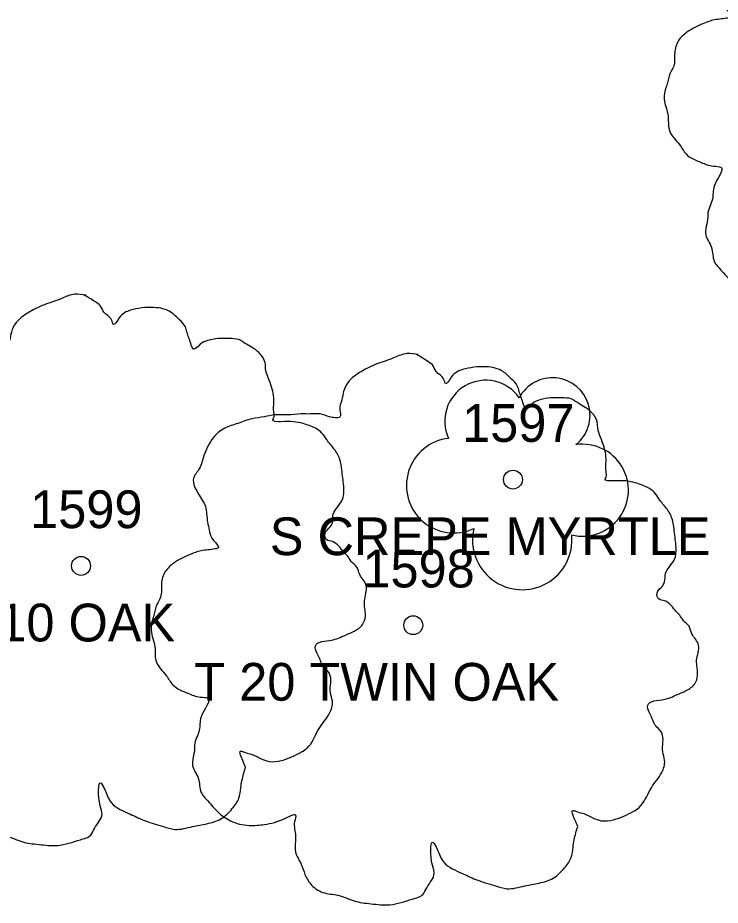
# Model space of a CAD drawing. Extents: x 1965304 to 1970247, y 1117014 to 1118201.
# Drawn here: x 1966620.94 to 1966639.53, y 1117434.12 to 1117457.62 of the extents above; entities that cross this region are included whole.
import ezdxf

# ---------------------------------------------------------------- set-up
doc = ezdxf.new("R2010")
doc.units = 0
doc.layers.add('RD_EX_VEG', color=7, linetype='Continuous')
doc.layers.add('RD_EX_VEG_txCode', color=7, linetype='Continuous')

msp = doc.modelspace()

# ---------------------------------------------------------------- linework, layer by layer
at = {"layer": 'RD_EX_VEG'}
for centre, radius in [((1966634.047, 1117445.393), 0.25), ((1966634.047, 1117445.393), 0.25), ((1966622.611, 1117443.108), 0.25), ((1966622.611, 1117443.108), 0.25), ((1966622.598, 1117443.09), 0.0001), ((1966622.598, 1117443.09), 0.0001), ((1966631.407, 1117441.538), 0.25), ((1966631.407, 1117441.538), 0.25), ((1966631.394, 1117441.519), 0.0001), ((1966631.394, 1117441.519), 0.0001)]:
    msp.add_circle(centre, radius, dxfattribs=at)
for centre, radius, start, end in [((1966633.325, 1117446.94), 1.084, 34.9763, 204.756), ((1966633.325, 1117446.94), 1.084, 34.9763, 204.756), ((1966635.092, 1117447.095), 0.995, 308.7626, 152.0467), ((1966635.092, 1117447.095), 0.995, 308.7626, 152.0467), ((1966632.483, 1117445.237), 1.257, 96.4518, 294.734), ((1966632.483, 1117445.237), 1.257, 96.4518, 294.734), ((1966635.886, 1117445.113), 1.218, 256.5667, 98.1046), ((1966635.886, 1117445.113), 1.218, 256.5667, 98.1046), ((1966634.292, 1117443.796), 1.318, 166.8827, 5.7589), ((1966634.292, 1117443.796), 1.318, 166.8827, 5.7589)]:
    msp.add_arc(centre, radius, start, end, dxfattribs=at)
for points in [[(1966645.126, 1117462.764), (1966644.826, 1117462.789), (1966644.501, 1117462.689), (1966644.251, 1117462.589), (1966644.026, 1117462.514), (1966643.801, 1117462.414), (1966643.501, 1117462.24), (1966643.276, 1117462.04), (1966643.151, 1117461.79), (1966643.101, 1117461.565), (1966643.052, 1117461.29), (1966643.052, 1117461.115), (1966642.927, 1117461.09), (1966642.777, 1117461.115), (1966642.527, 1117461.19), (1966642.277, 1117461.19), (1966642.027, 1117461.19), (1966641.677, 1117461.165), (1966641.327, 1117461.165), (1966641.052, 1117461.115), (1966640.728, 1117461.065), (1966640.353, 1117460.94), (1966640.003, 1117460.815), (1966639.703, 1117460.565), (1966639.453, 1117460.09), (1966639.328, 1117459.741), (1966639.178, 1117459.491), (1966639.328, 1117459.041), (1966639.503, 1117458.691), (1966639.528, 1117458.491), (1966639.603, 1117458.066), (1966639.703, 1117457.841), (1966639.828, 1117457.641), (1966639.753, 1117457.617), (1966639.378, 1117457.567), (1966639.078, 1117457.467), (1966638.653, 1117457.242), (1966638.429, 1117457.017), (1966638.329, 1117456.692), (1966638.304, 1117456.342), (1966638.204, 1117456.142), (1966638.129, 1117455.867), (1966638.104, 1117455.792), (1966638.054, 1117455.467), (1966638.154, 1117455.018), (1966638.179, 1117454.668), (1966638.304, 1117454.443), (1966638.454, 1117454.268), (1966638.628, 1117454.018), (1966639.028, 1117453.793), (1966639.353, 1117453.693), (1966639.553, 1117453.668), (1966639.378, 1117453.168), (1966639.328, 1117452.819), (1966639.203, 1117452.419), (1966639.203, 1117452.344), (1966639.153, 1117451.869), (1966639.303, 1117451.544), (1966639.378, 1117451.169), (1966639.553, 1117450.944), (1966639.828, 1117450.645), (1966640.153, 1117450.42), (1966640.653, 1117450.295), (1966641.052, 1117450.32), (1966641.627, 1117450.495), (1966641.877, 1117450.57), (1966641.852, 1117450.395), (1966641.877, 1117450.02), (1966641.877, 1117449.595), (1966642.027, 1117449.27), (1966642.127, 1117448.995), (1966642.277, 1117448.745), (1966642.602, 1117448.521), (1966643.002, 1117448.446), (1966643.426, 1117448.296), (1966643.876, 1117448.221), (1966644.376, 1117448.196), (1966644.976, 1117448.346), (1966645.251, 1117448.471), (1966645.351, 1117448.645), (1966645.55, 1117449.02), (1966645.5, 1117449.245), (1966645.525, 1117449.845), (1966645.625, 1117449.67), (1966645.8, 1117449.32), (1966646.3, 1117449.02), (1966646.7, 1117448.845), (1966647.175, 1117448.695), (1966647.475, 1117448.62), (1966647.949, 1117448.695), (1966648.324, 1117448.77), (1966648.699, 1117448.895), (1966648.999, 1117449.17), (1966649.174, 1117449.445), (1966649.224, 1117449.72), (1966649.299, 1117450.095), (1966649.349, 1117450.27)], [(1966645.126, 1117462.764), (1966644.826, 1117462.789), (1966644.501, 1117462.689), (1966644.251, 1117462.589), (1966644.026, 1117462.514), (1966643.801, 1117462.414), (1966643.501, 1117462.24), (1966643.276, 1117462.04), (1966643.151, 1117461.79), (1966643.101, 1117461.565), (1966643.052, 1117461.29), (1966643.052, 1117461.115), (1966642.927, 1117461.09), (1966642.777, 1117461.115), (1966642.527, 1117461.19), (1966642.277, 1117461.19), (1966642.027, 1117461.19), (1966641.677, 1117461.165), (1966641.327, 1117461.165), (1966641.052, 1117461.115), (1966640.728, 1117461.065), (1966640.353, 1117460.94), (1966640.003, 1117460.815), (1966639.703, 1117460.565), (1966639.453, 1117460.09), (1966639.328, 1117459.741), (1966639.178, 1117459.491), (1966639.328, 1117459.041), (1966639.503, 1117458.691), (1966639.528, 1117458.491), (1966639.603, 1117458.066), (1966639.703, 1117457.841), (1966639.828, 1117457.641), (1966639.753, 1117457.617), (1966639.378, 1117457.567), (1966639.078, 1117457.467), (1966638.653, 1117457.242), (1966638.429, 1117457.017), (1966638.329, 1117456.692), (1966638.304, 1117456.342), (1966638.204, 1117456.142), (1966638.129, 1117455.867), (1966638.104, 1117455.792), (1966638.054, 1117455.467), (1966638.154, 1117455.018), (1966638.179, 1117454.668), (1966638.304, 1117454.443), (1966638.454, 1117454.268), (1966638.628, 1117454.018), (1966639.028, 1117453.793), (1966639.353, 1117453.693), (1966639.553, 1117453.668), (1966639.378, 1117453.168), (1966639.328, 1117452.819), (1966639.203, 1117452.419), (1966639.203, 1117452.344), (1966639.153, 1117451.869), (1966639.303, 1117451.544), (1966639.378, 1117451.169), (1966639.553, 1117450.944), (1966639.828, 1117450.645), (1966640.153, 1117450.42), (1966640.653, 1117450.295), (1966641.052, 1117450.32), (1966641.627, 1117450.495), (1966641.877, 1117450.57), (1966641.852, 1117450.395), (1966641.877, 1117450.02), (1966641.877, 1117449.595), (1966642.027, 1117449.27), (1966642.127, 1117448.995), (1966642.277, 1117448.745), (1966642.602, 1117448.521), (1966643.002, 1117448.446), (1966643.426, 1117448.296), (1966643.876, 1117448.221), (1966644.376, 1117448.196), (1966644.976, 1117448.346), (1966645.251, 1117448.471), (1966645.351, 1117448.645), (1966645.55, 1117449.02), (1966645.5, 1117449.245), (1966645.525, 1117449.845), (1966645.625, 1117449.67), (1966645.8, 1117449.32), (1966646.3, 1117449.02), (1966646.7, 1117448.845), (1966647.175, 1117448.695), (1966647.475, 1117448.62), (1966647.949, 1117448.695), (1966648.324, 1117448.77), (1966648.699, 1117448.895), (1966648.999, 1117449.17), (1966649.174, 1117449.445), (1966649.224, 1117449.72), (1966649.299, 1117450.095), (1966649.349, 1117450.27)], [(1966622.743, 1117450.276), (1966622.443, 1117450.301), (1966622.118, 1117450.201), (1966621.868, 1117450.101), (1966621.643, 1117450.026), (1966621.418, 1117449.926), (1966621.118, 1117449.751), (1966620.893, 1117449.551), (1966620.768, 1117449.301), (1966620.718, 1117449.076), (1966620.669, 1117448.801), (1966620.669, 1117448.626), (1966620.544, 1117448.601), (1966620.394, 1117448.626), (1966620.144, 1117448.701), (1966619.894, 1117448.701), (1966619.644, 1117448.701), (1966619.294, 1117448.676), (1966618.944, 1117448.676), (1966618.669, 1117448.626), (1966618.345, 1117448.576), (1966617.97, 1117448.451), (1966617.62, 1117448.326), (1966617.32, 1117448.077), (1966617.07, 1117447.602), (1966616.945, 1117447.252), (1966616.795, 1117447.002), (1966616.945, 1117446.552), (1966617.12, 1117446.202), (1966617.145, 1117446.002), (1966617.22, 1117445.578), (1966617.32, 1117445.353), (1966617.445, 1117445.153), (1966617.37, 1117445.128), (1966616.995, 1117445.078), (1966616.695, 1117444.978), (1966616.27, 1117444.753), (1966616.046, 1117444.528), (1966615.946, 1117444.203), (1966615.921, 1117443.853), (1966615.821, 1117443.654), (1966615.746, 1117443.379), (1966615.721, 1117443.304), (1966615.671, 1117442.979), (1966615.771, 1117442.529), (1966615.796, 1117442.179), (1966615.921, 1117441.954), (1966616.071, 1117441.779), (1966616.245, 1117441.529), (1966616.645, 1117441.305), (1966616.97, 1117441.205), (1966617.17, 1117441.18), (1966616.995, 1117440.68), (1966616.945, 1117440.33), (1966616.82, 1117439.93), (1966616.82, 1117439.855), (1966616.77, 1117439.38), (1966616.92, 1117439.055), (1966616.995, 1117438.681), (1966617.17, 1117438.456), (1966617.445, 1117438.156), (1966617.77, 1117437.931), (1966618.27, 1117437.806), (1966618.669, 1117437.831), (1966619.244, 1117438.006), (1966619.494, 1117438.081), (1966619.469, 1117437.906), (1966619.494, 1117437.531), (1966619.494, 1117437.106), (1966619.644, 1117436.782), (1966619.744, 1117436.507), (1966619.894, 1117436.257), (1966620.219, 1117436.032), (1966620.619, 1117435.957), (1966621.043, 1117435.807), (1966621.493, 1117435.732), (1966621.993, 1117435.707), (1966622.593, 1117435.857), (1966622.868, 1117435.982), (1966622.968, 1117436.157), (1966623.167, 1117436.532), (1966623.117, 1117436.757), (1966623.142, 1117437.356), (1966623.242, 1117437.181), (1966623.417, 1117436.831), (1966623.917, 1117436.532), (1966624.317, 1117436.357), (1966624.792, 1117436.207), (1966625.092, 1117436.132), (1966625.566, 1117436.207), (1966625.941, 1117436.282), (1966626.316, 1117436.407), (1966626.616, 1117436.682), (1966626.791, 1117436.956), (1966626.841, 1117437.231), (1966626.916, 1117437.606), (1966626.966, 1117437.781)], [(1966622.743, 1117450.276), (1966622.443, 1117450.301), (1966622.118, 1117450.201), (1966621.868, 1117450.101), (1966621.643, 1117450.026), (1966621.418, 1117449.926), (1966621.118, 1117449.751), (1966620.893, 1117449.551), (1966620.768, 1117449.301), (1966620.718, 1117449.076), (1966620.669, 1117448.801), (1966620.669, 1117448.626), (1966620.544, 1117448.601), (1966620.394, 1117448.626), (1966620.144, 1117448.701), (1966619.894, 1117448.701), (1966619.644, 1117448.701), (1966619.294, 1117448.676), (1966618.944, 1117448.676), (1966618.669, 1117448.626), (1966618.345, 1117448.576), (1966617.97, 1117448.451), (1966617.62, 1117448.326), (1966617.32, 1117448.077), (1966617.07, 1117447.602), (1966616.945, 1117447.252), (1966616.795, 1117447.002), (1966616.945, 1117446.552), (1966617.12, 1117446.202), (1966617.145, 1117446.002), (1966617.22, 1117445.578), (1966617.32, 1117445.353), (1966617.445, 1117445.153), (1966617.37, 1117445.128), (1966616.995, 1117445.078), (1966616.695, 1117444.978), (1966616.27, 1117444.753), (1966616.046, 1117444.528), (1966615.946, 1117444.203), (1966615.921, 1117443.853), (1966615.821, 1117443.654), (1966615.746, 1117443.379), (1966615.721, 1117443.304), (1966615.671, 1117442.979), (1966615.771, 1117442.529), (1966615.796, 1117442.179), (1966615.921, 1117441.954), (1966616.071, 1117441.779), (1966616.245, 1117441.529), (1966616.645, 1117441.305), (1966616.97, 1117441.205), (1966617.17, 1117441.18), (1966616.995, 1117440.68), (1966616.945, 1117440.33), (1966616.82, 1117439.93), (1966616.82, 1117439.855), (1966616.77, 1117439.38), (1966616.92, 1117439.055), (1966616.995, 1117438.681), (1966617.17, 1117438.456), (1966617.445, 1117438.156), (1966617.77, 1117437.931), (1966618.27, 1117437.806), (1966618.669, 1117437.831), (1966619.244, 1117438.006), (1966619.494, 1117438.081), (1966619.469, 1117437.906), (1966619.494, 1117437.531), (1966619.494, 1117437.106), (1966619.644, 1117436.782), (1966619.744, 1117436.507), (1966619.894, 1117436.257), (1966620.219, 1117436.032), (1966620.619, 1117435.957), (1966621.043, 1117435.807), (1966621.493, 1117435.732), (1966621.993, 1117435.707), (1966622.593, 1117435.857), (1966622.868, 1117435.982), (1966622.968, 1117436.157), (1966623.167, 1117436.532), (1966623.117, 1117436.757), (1966623.142, 1117437.356), (1966623.242, 1117437.181), (1966623.417, 1117436.831), (1966623.917, 1117436.532), (1966624.317, 1117436.357), (1966624.792, 1117436.207), (1966625.092, 1117436.132), (1966625.566, 1117436.207), (1966625.941, 1117436.282), (1966626.316, 1117436.407), (1966626.616, 1117436.682), (1966626.791, 1117436.956), (1966626.841, 1117437.231), (1966626.916, 1117437.606), (1966626.966, 1117437.781)], [(1966626.966, 1117437.781), (1966626.891, 1117437.956), (1966626.841, 1117438.206), (1966626.916, 1117438.181), (1966627.091, 1117438.131), (1966627.366, 1117438.006), (1966627.591, 1117437.931), (1966627.915, 1117437.956), (1966628.19, 1117438.056), (1966628.64, 1117438.331), (1966628.915, 1117438.806), (1966629.19, 1117439.205), (1966629.265, 1117439.53), (1966629.215, 1117439.755), (1966629.19, 1117440.255), (1966628.99, 1117440.505), (1966628.94, 1117440.63), (1966628.84, 1117441.03), (1966628.915, 1117441.08), (1966629.19, 1117441.13), (1966629.565, 1117441.255), (1966629.84, 1117441.379), (1966630.064, 1117441.554), (1966630.139, 1117441.779), (1966630.114, 1117442.179), (1966630.164, 1117442.579), (1966630.089, 1117442.729), (1966629.989, 1117442.879), (1966629.914, 1117443.079), (1966629.765, 1117443.229), (1966629.665, 1117443.379), (1966629.565, 1117443.479), (1966629.44, 1117443.629), (1966629.265, 1117443.753), (1966629.115, 1117443.803), (1966629.065, 1117443.953), (1966629.215, 1117444.153), (1966629.265, 1117444.253), (1966629.29, 1117444.478), (1966629.515, 1117444.828), (1966629.565, 1117445.228), (1966629.515, 1117445.653), (1966629.465, 1117445.928), (1966629.315, 1117446.202), (1966629.115, 1117446.452), (1966628.99, 1117446.627), (1966628.815, 1117446.752), (1966628.49, 1117446.877), (1966628.24, 1117446.927), (1966627.89, 1117446.927), (1966627.69, 1117446.977), (1966627.715, 1117447.027), (1966627.715, 1117447.177), (1966627.715, 1117447.452), (1966627.64, 1117447.902), (1966627.491, 1117448.401), (1966627.491, 1117448.426), (1966627.391, 1117448.676), (1966627.166, 1117448.876), (1966626.991, 1117448.976), (1966626.791, 1117449.101), (1966626.541, 1117449.126), (1966626.241, 1117449.126), (1966625.966, 1117449.076), (1966625.766, 1117448.976), (1966625.591, 1117448.851), (1966625.516, 1117449.001), (1966625.416, 1117449.301), (1966625.366, 1117449.451), (1966625.217, 1117449.626), (1966624.992, 1117449.826), (1966624.542, 1117449.951), (1966623.917, 1117449.876), (1966623.617, 1117449.676), (1966623.467, 1117449.501), (1966623.417, 1117449.626), (1966623.217, 1117449.826), (1966623.117, 1117450.001), (1966622.943, 1117450.126), (1966622.793, 1117450.226), (1966622.693, 1117450.276)], [(1966626.966, 1117437.781), (1966626.891, 1117437.956), (1966626.841, 1117438.206), (1966626.916, 1117438.181), (1966627.091, 1117438.131), (1966627.366, 1117438.006), (1966627.591, 1117437.931), (1966627.915, 1117437.956), (1966628.19, 1117438.056), (1966628.64, 1117438.331), (1966628.915, 1117438.806), (1966629.19, 1117439.205), (1966629.265, 1117439.53), (1966629.215, 1117439.755), (1966629.19, 1117440.255), (1966628.99, 1117440.505), (1966628.94, 1117440.63), (1966628.84, 1117441.03), (1966628.915, 1117441.08), (1966629.19, 1117441.13), (1966629.565, 1117441.255), (1966629.84, 1117441.379), (1966630.064, 1117441.554), (1966630.139, 1117441.779), (1966630.114, 1117442.179), (1966630.164, 1117442.579), (1966630.089, 1117442.729), (1966629.989, 1117442.879), (1966629.914, 1117443.079), (1966629.765, 1117443.229), (1966629.665, 1117443.379), (1966629.565, 1117443.479), (1966629.44, 1117443.629), (1966629.265, 1117443.753), (1966629.115, 1117443.803), (1966629.065, 1117443.953), (1966629.215, 1117444.153), (1966629.265, 1117444.253), (1966629.29, 1117444.478), (1966629.515, 1117444.828), (1966629.565, 1117445.228), (1966629.515, 1117445.653), (1966629.465, 1117445.928), (1966629.315, 1117446.202), (1966629.115, 1117446.452), (1966628.99, 1117446.627), (1966628.815, 1117446.752), (1966628.49, 1117446.877), (1966628.24, 1117446.927), (1966627.89, 1117446.927), (1966627.69, 1117446.977), (1966627.715, 1117447.027), (1966627.715, 1117447.177), (1966627.715, 1117447.452), (1966627.64, 1117447.902), (1966627.491, 1117448.401), (1966627.491, 1117448.426), (1966627.391, 1117448.676), (1966627.166, 1117448.876), (1966626.991, 1117448.976), (1966626.791, 1117449.101), (1966626.541, 1117449.126), (1966626.241, 1117449.126), (1966625.966, 1117449.076), (1966625.766, 1117448.976), (1966625.591, 1117448.851), (1966625.516, 1117449.001), (1966625.416, 1117449.301), (1966625.366, 1117449.451), (1966625.217, 1117449.626), (1966624.992, 1117449.826), (1966624.542, 1117449.951), (1966623.917, 1117449.876), (1966623.617, 1117449.676), (1966623.467, 1117449.501), (1966623.417, 1117449.626), (1966623.217, 1117449.826), (1966623.117, 1117450.001), (1966622.943, 1117450.126), (1966622.793, 1117450.226), (1966622.693, 1117450.276)], [(1966631.539, 1117448.705), (1966631.239, 1117448.73), (1966630.914, 1117448.63), (1966630.664, 1117448.53), (1966630.439, 1117448.455), (1966630.214, 1117448.355), (1966629.914, 1117448.18), (1966629.689, 1117447.98), (1966629.564, 1117447.731), (1966629.514, 1117447.506), (1966629.464, 1117447.231), (1966629.464, 1117447.056), (1966629.34, 1117447.031), (1966629.19, 1117447.056), (1966628.94, 1117447.131), (1966628.69, 1117447.131), (1966628.44, 1117447.131), (1966628.09, 1117447.106), (1966627.74, 1117447.106), (1966627.465, 1117447.056), (1966627.14, 1117447.006), (1966626.766, 1117446.881), (1966626.416, 1117446.756), (1966626.116, 1117446.506), (1966625.866, 1117446.031), (1966625.741, 1117445.681), (1966625.591, 1117445.432), (1966625.741, 1117444.982), (1966625.916, 1117444.632), (1966625.941, 1117444.432), (1966626.016, 1117444.007), (1966626.116, 1117443.782), (1966626.241, 1117443.582), (1966626.166, 1117443.557), (1966625.791, 1117443.507), (1966625.491, 1117443.407), (1966625.066, 1117443.183), (1966624.841, 1117442.958), (1966624.741, 1117442.633), (1966624.717, 1117442.283), (1966624.617, 1117442.083), (1966624.542, 1117441.808), (1966624.517, 1117441.733), (1966624.467, 1117441.408), (1966624.567, 1117440.958), (1966624.592, 1117440.609), (1966624.717, 1117440.384), (1966624.866, 1117440.209), (1966625.041, 1117439.959), (1966625.441, 1117439.734), (1966625.766, 1117439.634), (1966625.966, 1117439.609), (1966625.791, 1117439.109), (1966625.741, 1117438.759), (1966625.616, 1117438.36), (1966625.616, 1117438.285), (1966625.566, 1117437.81), (1966625.716, 1117437.485), (1966625.791, 1117437.11), (1966625.966, 1117436.885), (1966626.241, 1117436.585), (1966626.566, 1117436.361), (1966627.066, 1117436.236), (1966627.465, 1117436.261), (1966628.04, 1117436.435), (1966628.29, 1117436.51), (1966628.265, 1117436.336), (1966628.29, 1117435.961), (1966628.29, 1117435.536), (1966628.44, 1117435.211), (1966628.54, 1117434.936), (1966628.69, 1117434.686), (1966629.015, 1117434.461), (1966629.414, 1117434.386), (1966629.839, 1117434.236), (1966630.289, 1117434.161), (1966630.789, 1117434.136), (1966631.389, 1117434.286), (1966631.663, 1117434.411), (1966631.763, 1117434.586), (1966631.963, 1117434.961), (1966631.913, 1117435.186), (1966631.938, 1117435.786), (1966632.038, 1117435.611), (1966632.213, 1117435.261), (1966632.713, 1117434.961), (1966633.113, 1117434.786), (1966633.588, 1117434.636), (1966633.888, 1117434.561), (1966634.362, 1117434.636), (1966634.737, 1117434.711), (1966635.112, 1117434.836), (1966635.412, 1117435.111), (1966635.587, 1117435.386), (1966635.637, 1117435.661), (1966635.712, 1117436.036), (1966635.762, 1117436.211)], [(1966631.539, 1117448.705), (1966631.239, 1117448.73), (1966630.914, 1117448.63), (1966630.664, 1117448.53), (1966630.439, 1117448.455), (1966630.214, 1117448.355), (1966629.914, 1117448.18), (1966629.689, 1117447.98), (1966629.564, 1117447.731), (1966629.514, 1117447.506), (1966629.464, 1117447.231), (1966629.464, 1117447.056), (1966629.34, 1117447.031), (1966629.19, 1117447.056), (1966628.94, 1117447.131), (1966628.69, 1117447.131), (1966628.44, 1117447.131), (1966628.09, 1117447.106), (1966627.74, 1117447.106), (1966627.465, 1117447.056), (1966627.14, 1117447.006), (1966626.766, 1117446.881), (1966626.416, 1117446.756), (1966626.116, 1117446.506), (1966625.866, 1117446.031), (1966625.741, 1117445.681), (1966625.591, 1117445.432), (1966625.741, 1117444.982), (1966625.916, 1117444.632), (1966625.941, 1117444.432), (1966626.016, 1117444.007), (1966626.116, 1117443.782), (1966626.241, 1117443.582), (1966626.166, 1117443.557), (1966625.791, 1117443.507), (1966625.491, 1117443.407), (1966625.066, 1117443.183), (1966624.841, 1117442.958), (1966624.741, 1117442.633), (1966624.717, 1117442.283), (1966624.617, 1117442.083), (1966624.542, 1117441.808), (1966624.517, 1117441.733), (1966624.467, 1117441.408), (1966624.567, 1117440.958), (1966624.592, 1117440.609), (1966624.717, 1117440.384), (1966624.866, 1117440.209), (1966625.041, 1117439.959), (1966625.441, 1117439.734), (1966625.766, 1117439.634), (1966625.966, 1117439.609), (1966625.791, 1117439.109), (1966625.741, 1117438.759), (1966625.616, 1117438.36), (1966625.616, 1117438.285), (1966625.566, 1117437.81), (1966625.716, 1117437.485), (1966625.791, 1117437.11), (1966625.966, 1117436.885), (1966626.241, 1117436.585), (1966626.566, 1117436.361), (1966627.066, 1117436.236), (1966627.465, 1117436.261), (1966628.04, 1117436.435), (1966628.29, 1117436.51), (1966628.265, 1117436.336), (1966628.29, 1117435.961), (1966628.29, 1117435.536), (1966628.44, 1117435.211), (1966628.54, 1117434.936), (1966628.69, 1117434.686), (1966629.015, 1117434.461), (1966629.414, 1117434.386), (1966629.839, 1117434.236), (1966630.289, 1117434.161), (1966630.789, 1117434.136), (1966631.389, 1117434.286), (1966631.663, 1117434.411), (1966631.763, 1117434.586), (1966631.963, 1117434.961), (1966631.913, 1117435.186), (1966631.938, 1117435.786), (1966632.038, 1117435.611), (1966632.213, 1117435.261), (1966632.713, 1117434.961), (1966633.113, 1117434.786), (1966633.588, 1117434.636), (1966633.888, 1117434.561), (1966634.362, 1117434.636), (1966634.737, 1117434.711), (1966635.112, 1117434.836), (1966635.412, 1117435.111), (1966635.587, 1117435.386), (1966635.637, 1117435.661), (1966635.712, 1117436.036), (1966635.762, 1117436.211)], [(1966635.762, 1117436.211), (1966635.687, 1117436.386), (1966635.637, 1117436.635), (1966635.712, 1117436.61), (1966635.887, 1117436.56), (1966636.162, 1117436.435), (1966636.386, 1117436.361), (1966636.711, 1117436.386), (1966636.986, 1117436.485), (1966637.436, 1117436.76), (1966637.711, 1117437.235), (1966637.986, 1117437.635), (1966638.061, 1117437.96), (1966638.011, 1117438.185), (1966637.986, 1117438.684), (1966637.786, 1117438.934), (1966637.736, 1117439.059), (1966637.636, 1117439.459), (1966637.711, 1117439.509), (1966637.986, 1117439.559), (1966638.361, 1117439.684), (1966638.635, 1117439.809), (1966638.86, 1117439.984), (1966638.935, 1117440.209), (1966638.91, 1117440.609), (1966638.96, 1117441.008), (1966638.885, 1117441.158), (1966638.785, 1117441.308), (1966638.71, 1117441.508), (1966638.56, 1117441.658), (1966638.461, 1117441.808), (1966638.361, 1117441.908), (1966638.236, 1117442.058), (1966638.061, 1117442.183), (1966637.911, 1117442.233), (1966637.861, 1117442.383), (1966638.011, 1117442.583), (1966638.061, 1117442.683), (1966638.086, 1117442.908), (1966638.311, 1117443.257), (1966638.361, 1117443.657), (1966638.311, 1117444.082), (1966638.261, 1117444.357), (1966638.111, 1117444.632), (1966637.911, 1117444.882), (1966637.786, 1117445.057), (1966637.611, 1117445.182), (1966637.286, 1117445.307), (1966637.036, 1117445.357), (1966636.686, 1117445.357), (1966636.486, 1117445.407), (1966636.511, 1117445.457), (1966636.511, 1117445.606), (1966636.511, 1117445.881), (1966636.436, 1117446.331), (1966636.286, 1117446.831), (1966636.286, 1117446.856), (1966636.186, 1117447.106), (1966635.962, 1117447.306), (1966635.787, 1117447.406), (1966635.587, 1117447.531), (1966635.337, 1117447.556), (1966635.037, 1117447.556), (1966634.762, 1117447.506), (1966634.562, 1117447.406), (1966634.387, 1117447.281), (1966634.312, 1117447.431), (1966634.212, 1117447.731), (1966634.162, 1117447.88), (1966634.012, 1117448.055), (1966633.788, 1117448.255), (1966633.338, 1117448.38), (1966632.713, 1117448.305), (1966632.413, 1117448.105), (1966632.263, 1117447.93), (1966632.213, 1117448.055), (1966632.013, 1117448.255), (1966631.913, 1117448.43), (1966631.738, 1117448.555), (1966631.589, 1117448.655), (1966631.489, 1117448.705)], [(1966635.762, 1117436.211), (1966635.687, 1117436.386), (1966635.637, 1117436.635), (1966635.712, 1117436.61), (1966635.887, 1117436.56), (1966636.162, 1117436.435), (1966636.386, 1117436.361), (1966636.711, 1117436.386), (1966636.986, 1117436.485), (1966637.436, 1117436.76), (1966637.711, 1117437.235), (1966637.986, 1117437.635), (1966638.061, 1117437.96), (1966638.011, 1117438.185), (1966637.986, 1117438.684), (1966637.786, 1117438.934), (1966637.736, 1117439.059), (1966637.636, 1117439.459), (1966637.711, 1117439.509), (1966637.986, 1117439.559), (1966638.361, 1117439.684), (1966638.635, 1117439.809), (1966638.86, 1117439.984), (1966638.935, 1117440.209), (1966638.91, 1117440.609), (1966638.96, 1117441.008), (1966638.885, 1117441.158), (1966638.785, 1117441.308), (1966638.71, 1117441.508), (1966638.56, 1117441.658), (1966638.461, 1117441.808), (1966638.361, 1117441.908), (1966638.236, 1117442.058), (1966638.061, 1117442.183), (1966637.911, 1117442.233), (1966637.861, 1117442.383), (1966638.011, 1117442.583), (1966638.061, 1117442.683), (1966638.086, 1117442.908), (1966638.311, 1117443.257), (1966638.361, 1117443.657), (1966638.311, 1117444.082), (1966638.261, 1117444.357), (1966638.111, 1117444.632), (1966637.911, 1117444.882), (1966637.786, 1117445.057), (1966637.611, 1117445.182), (1966637.286, 1117445.307), (1966637.036, 1117445.357), (1966636.686, 1117445.357), (1966636.486, 1117445.407), (1966636.511, 1117445.457), (1966636.511, 1117445.606), (1966636.511, 1117445.881), (1966636.436, 1117446.331), (1966636.286, 1117446.831), (1966636.286, 1117446.856), (1966636.186, 1117447.106), (1966635.962, 1117447.306), (1966635.787, 1117447.406), (1966635.587, 1117447.531), (1966635.337, 1117447.556), (1966635.037, 1117447.556), (1966634.762, 1117447.506), (1966634.562, 1117447.406), (1966634.387, 1117447.281), (1966634.312, 1117447.431), (1966634.212, 1117447.731), (1966634.162, 1117447.88), (1966634.012, 1117448.055), (1966633.788, 1117448.255), (1966633.338, 1117448.38), (1966632.713, 1117448.305), (1966632.413, 1117448.105), (1966632.263, 1117447.93), (1966632.213, 1117448.055), (1966632.013, 1117448.255), (1966631.913, 1117448.43), (1966631.738, 1117448.555), (1966631.589, 1117448.655), (1966631.489, 1117448.705)]]:
    msp.add_spline(points, degree=3, dxfattribs=at)

# ---------------------------------------------------------------- texts
at = {"layer": 'RD_EX_VEG_txCode'}
for s, p in [('1597', (1966632.7, 1117446.393)), ('1597', (1966632.7, 1117446.393)), ('1599', (1966621.264, 1117444.108)), ('1599', (1966621.264, 1117444.108)), ('S CREPE MYRTLE', (1966627.609, 1117443.393)), ('S CREPE MYRTLE', (1966627.609, 1117443.393)), ('1598', (1966630.06, 1117442.538)), ('1598', (1966630.06, 1117442.538)), ('T 10 OAK', (1966619.233, 1117441.108)), ('T 10 OAK', (1966619.233, 1117441.108)), ('T 20 TWIN OAK', (1966625.611, 1117439.538)), ('T 20 TWIN OAK', (1966625.611, 1117439.538))]:
    msp.add_text(s, height=1, dxfattribs=at).set_placement(p)

doc.saveas('drawing.dxf')
